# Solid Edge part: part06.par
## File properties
Author: Robert a Rhodes jr
Template: normal.par
Last saved by: CADCIM
Revision: 8
Application: Solid Edge
Accuracy: 0.99
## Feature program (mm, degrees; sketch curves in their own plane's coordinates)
sketch for "unnamed Protrusion 1" plane through (0, 0, 0) normal (0, -1, 0) x-axis (1, 0, 0)
  arc centre (60, 0) radius 30 from (60, 30) to (60, -30) cw
  line (104, -30) -> (60, -30)
  line (104, 18) -> (104, -30)
  line (164, 18) -> (104, 18)
  line (164, -4) -> (164, 18)
  line (182, -4) -> (164, -4)
  line (182, -4) -> (182, 36)
  line (142, 36) -> (182, 36)
  line (142, 30) -> (142, 36)
  line (60, 30) -> (142, 30)
extrude "unnamed Protrusion 1" add finite 54 symmetric
sketch for "ExtrudedProtrusion_6" #1 plane through (0, 0, 0) normal (0, -1, 0) x-axis (1, 0, 0)
  arc centre (60, 0) radius 30 from (60, 30) to (60, -30) ccw
  arc centre (60, 0) radius 30 from (60, 30) to (60, -30) cw
sketch for "ExtrudedProtrusion_6" #2 plane through (0, 0, 0) normal (0, -1, 0) x-axis (1, 0, 0)
  circle centre (60, 0) radius 18
extrude "ExtrudedProtrusion_6" add finite 66 symmetric
sketch for "ExtrudedProtrusion_7" plane through (0, 0, 0) normal (0, -1, 0) x-axis (1, 0, 0)
  line (104, -30) -> (164, -4)
  line (164, -4) -> (164, 18)
  line (164, 18) -> (104, 18)
  line (104, 18) -> (104, -30)
extrude "ExtrudedProtrusion_7" add finite 18 symmetric
sketch for "ExtrudedProtrusion_8" plane through (0, 0, 0) normal (0, -1, 0) x-axis (1, 0, 0)
  line (200, 76) -> (200, -4)
  line (200, -4) -> (182, -4)
  line (182, -4) -> (182, 36)
  line (182, 76) -> (182, 36)
  line (182, 76) -> (200, 76)
extrude "ExtrudedProtrusion_8" add finite 92 symmetric
sketch for "ExtrudedProtrusion_9" plane through (0, 0, 0) normal (0, -1, 0) x-axis (1, 0, 0)
  line (142, 36) -> (182, 76)
  line (182, 76) -> (182, 36)
  line (142, 36) -> (182, 36)
extrude "ExtrudedProtrusion_9" add finite 12 symmetric
sketch for "unnamed Hole 1" plane through (200, 0, 36) normal (1, 0, 0) x-axis (0, 1, 0)
hole "unnamed Hole 1" through
sketch for "Hole_1" plane through (200, 0, 36) normal (1, 0, 0) x-axis (0, 1, 0)
  hole centre (-30, 22) bore radius 8
hole "Hole_1" diameter 16 through
pattern "unnamed Pattern 1" of "unnamed Hole 1", "Hole_1"
fillet "unnamed Round 1"
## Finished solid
Body 1: solid body, 34 faces, 81 edges, 46 vertices.
  Faces by surface: plane 28, cylinder 6
  Edges by curve: line 67, circle 14
Bounding box of the edges (mm): 170.000 x 92.000 x 106.000, from (30, -46, -30) to (200, 46, 76).
Cylindrical faces by radius (mm): R8 x2, R16 x2, R18 x1, R30 x1
Planar faces by outward normal: +x 3, +y 5, +z 4, -x 5, -y 5, -z 4, oblique 2
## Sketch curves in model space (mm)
circle centre (60, 0, 0) radius 18
line (182, 0, -4) -> (164, 0, -4)
line (104, 0, -30) -> (60, 0, -30)
arc centre (60, 0, 0) radius 30 from (60, 0, 30) through (30.0132, 0, -0.889) to (60, 0, -30)
arc centre (60, 0, 0) radius 30 from (60, 0, 30) through (89.9868, 0, -0.889) to (60, 0, -30)
line (142, 0, 36) -> (182, 0, 76)
line (142, 0, 36) -> (182, 0, 36)
line (104, 0, -30) -> (164, 0, -4)
line (182, 0, 76) -> (182, 0, 36)
line (182, 0, -4) -> (182, 0, 36)
line (142, 0, 30) -> (142, 0, 36)
line (60, 0, 30) -> (142, 0, 30)
line (104, 0, 18) -> (104, 0, -30)
line (164, 0, 18) -> (104, 0, 18)
line (164, 0, -4) -> (164, 0, 18)
line (200, 0, -4) -> (182, 0, -4)
line (200, 0, 76) -> (200, 0, -4)
line (182, 0, 76) -> (200, 0, 76)
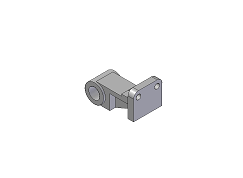
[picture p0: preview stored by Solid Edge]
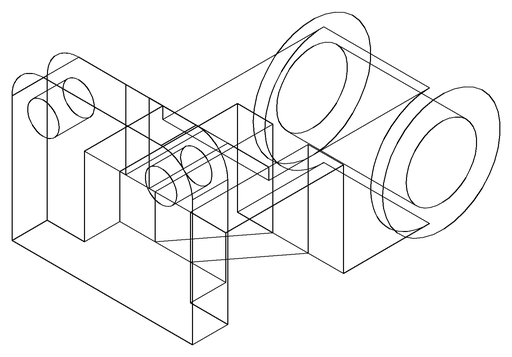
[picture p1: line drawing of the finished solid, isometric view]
